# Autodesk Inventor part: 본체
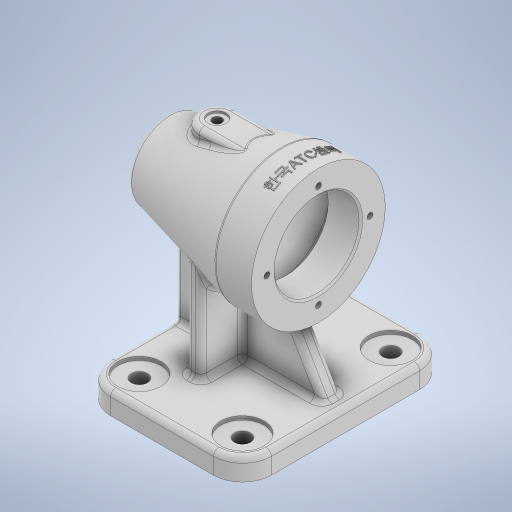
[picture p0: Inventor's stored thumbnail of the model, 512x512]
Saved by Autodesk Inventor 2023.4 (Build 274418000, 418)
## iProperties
Created: 2024-12
Part Number: 본체
Material: 일반
Document SubType Name: Modeling
Designer: EDU
Density: 1 g/cm^3
Appearance: 기본값
Author: EDU
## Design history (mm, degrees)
sketch "스케치1"
  geometry: L1 (0, 0)-(0, 21); L2 (0, 21)-(64, 37); L3 (0, 0)-(84, 0); L4 (-16.8, 0)-(100.8, 0) reference; L5 (64, 37)-(84, 37); L6 (84, 37)-(84, 0); 1 further point
  constraints: 10 end point, 2 horizontal, 1 coincident, 1 horizontal alignment, 1 perpendicular, 1 vertical
  dimensions: "d0" = 21 distance of L1.start L1.end; "d4" = 64 horizontal distance of L1.end L2.end; "d13" = 20 distance of L2.end L5.end; "d14" = 37 distance of L5.end L3.end
revolve "회전1" sketch "스케치1" stored, may be unused: angle "d6" = 90 deg
feature "쉘2" dims "d19" = 18, "d20" = 21, "d21" = 5
sketch "스케치5"
  geometry: C1 r 23.5 at (0, 0); 1 further point
  constraints: 1 centre point, 1 coincident
  dimensions: "d22" = 47 diameter of C1
extrude "돌출2" cut sketch "스케치5" distance "d23" = 18; taper "d24" = 0 deg
sketch "스케치6"
  geometry: C1 r 17.5 at (0, 0); 1 further point
  constraints: 1 centre point, 1 coincident
  dimensions: "d25" = 35 diameter of C1
extrude "돌출3" cut sketch "스케치6" distance "d26" = 10; taper "d27" = 0 deg
sketch "스케치7"
  geometry: C1 r 15.5 at (0, 0); 1 further point
  constraints: 1 centre point, 1 coincident
  dimensions: "d28" = 31 diameter of C1
extrude "돌출4" cut sketch "스케치7" distance "d29" = 3; taper "d30" = 0 deg
fillet "모깎기1" dims "d31" = 3
fillet "모깎기2" dims "d32" = 0.3
chamfer "모따기1" distance "d33" = 1; stored, may be unused: second distance "d34" = 2, angle "d35" = 45 deg
fillet "모깎기3" dims "d36" = 3
fillet "모깎기4" dims "d37" = 5
chamfer "모따기2" distance "d38" = 1; stored, may be unused: second distance "d39" = 2, angle "d40" = 45 deg
sketch "스케치8"
  geometry: C1 r 37 at (0, 0) reference; C2 r 24.5 at (0, 0) reference; A1 r 28.5 centre (0, 0) between (0, 28.5) and (0, -28.5); 3 further points
  constraints: 4 point on circle, 2 horizontal alignment, 2 vertical alignment, 1 centre point, 1 coincident
  dimensions: "d41" = 57 diameter of A1
hole "구멍1" sketch "스케치8" at (0, 28.5), (-28.5, 0), (28.5, 0), (0, -28.5) diameter "d42" = 3.242; stored, may be unused: countersink angle "d46" = 90 deg, drill point angle "d48" = 118 deg; dims "d43" = 8, "d44" = 4, "d45" = 2, "d47" = 10
node "작업 평면1"
sketch "스케치9"
  geometry: L1 (-10, 57)-(-99, 57); L2 (-99, 57)-(-99, -57); L3 (-99, -57)-(-10, -57); L4 (-10, -57)-(-10, 57); L5 (-84, 37)-(-84, -37) reference; 2 further points
  constraints: 8 end point, 2 parallel, 1 horizontal, 1 horizontal alignment, 1 midpoint, 1 perpendicular
  dimensions: "d50" = 114 distance between parallel lines of L1 L3; "d51" = 89 distance between parallel lines of L2 L4; "d52" = 15 distance between parallel lines of L2 L5
extrude "돌출5" join sketch "스케치9" distance "d53" = 12; taper "d54" = 0 deg
fillet "모깎기5" dims "d55" = 16
sketch "스케치10"
  geometry: L1 (83, 57)-(26, 57) reference; L2 (99, -41)-(99, 41) reference; L3 (26, -57)-(83, -57) reference; L4 (10, 41)-(10, -41) reference; A1 r 16 centre (26, 41) between (26, 57) and (10, 41) reference; A2 r 16 centre (83, 41) between (99, 41) and (83, 57) reference; A3 r 16 centre (83, -41) between (83, -57) and (99, -41) reference; A4 r 16 centre (26, -41) between (10, -41) and (26, -57) reference; 5 further points
  constraints: 4 coincident
hole "구멍2" sketch "스케치10" at (26, -41), (26, 41), (83, 41), (83, -41) diameter "d56" = 9; stored, may be unused: countersink angle "d60" = 90 deg, drill point angle "d62" = 118 deg; dims "d57" = 8, "d58" = 24, "d59" = 2, "d61" = 10
sketch "스케치11"
  geometry: L1 (83, 57)-(26, 57) reference; L2 (99, -41)-(99, 41) reference; L3 (26, -57)-(83, -57) reference; L4 (10, 41)-(10, -41) reference; L5 (10, 41)-(10, -41) reference; L6 (10, -5)-(39, -5); L7 (39, -5)-(39, -28); L8 (39, -28)-(47, -28); L9 (47, -28)-(47, 28); L10 (47, 28)-(39, 28); L11 (39, 28)-(39, 5); L12 (39, 5)-(10, 5); C1 r 4.5 at (83, 41) reference; C2 r 4.5 at (26, -41) reference; C3 r 4.5 at (26, 41) reference; C4 r 4.5 at (83, -41) reference; A1 r 16 centre (26, 41) between (26, 57) and (10, 41) reference; A2 r 16 centre (83, 41) between (99, 41) and (83, 57) reference; A3 r 16 centre (83, -41) between (83, -57) and (99, -41) reference; A4 r 16 centre (26, -41) between (10, -41) and (26, -57) reference; 5 further points
  constraints: 14 end point, 5 perpendicular, 4 point on line, 2 midpoint, 1 horizontal
  dimensions: "d63" = 10 distance between parallel lines of L6 L12; "d64" = 8 distance of L7.end L8.end; "d65" = 29 distance between parallel lines of L7 L4; "d66" = 56 distance between parallel lines of L10 L8; "d67" = 5 distance from line of L12 point (10, 0); "d68" = 28 distance from line of point (10, 0) L10
extrude "돌출6" join sketch "스케치11" stored distance "d69" = 12; taper "d70" = 0 deg
sketch "스케치12"
  geometry: L1 (47, -70)-(47, -16.987) reference; L2 (99, -70)-(99, -82) reference; L3 (83, -70)-(26, -70) reference; L4 (83, -70)-(99, -70) reference; L5 (99, -70)-(99, -82) reference; L6 (99, -82)-(83, -82) reference; L7 (83, -82)-(83, -70) reference; L8 (64, -37)-(84, -37) reference; L9 (0, -21)-(64, -37) reference; L10 (71, -70)-(95, -70) reference; L11 (92, -70)-(72.947, -37); 1 further point
  constraints: 2 end point, 2 point on line
  dimensions: "d71" = 7 distance of L2.start L11.start; "d72" = 60 deg angle of L4 L11
feature "리브1" sketch "스케치12" dims "d73" = 1, "d74" = 10, "d75" = 0, "d76" = 0, "d77" = 1, "d78" = 1
node "작업 평면2"
sketch "스케치13"
  geometry: L1 (-10, 37)-(-10, -37) reference; 3 further points
  constraints: 1 horizontal alignment, 1 midpoint, 1 other
  dimensions: "d79" = 9 distance from line of L1 point (-1, 0)
feature "엠보싱1" sketch "스케치13" dims "d0" = 21, "d80" = 0.5, "d81" = 0
node "작업 평면3"
sketch "스케치14"
  geometry: L1 (84, -37)-(84, 37) reference; L2 (28, 10)-(58, 10); L3 (28, -10)-(58, -10); L4 (58, 10)-(58, -10); A1 r 10 centre (28, 0) between (28, 10) and (28, -10); 2 further points
  constraints: 6 end point, 2 horizontal, 2 point on circle, 2 tangent, 1 centre point, 1 horizontal alignment, 1 midpoint, 1 vertical
  dimensions: "d83" = 20 diameter of A1; "d84" = 56 distance from line of L1 A1.centre; "d85" = 30 distance of L3.start L3.end
extrude "돌출7" join sketch "스케치14" stored distance "d86" = 10; taper "d87" = 0 deg
sketch "스케치15"
  geometry: L1 (84, -37)-(84, 37) reference; 2 further points
  constraints: 1 horizontal alignment
  dimensions: "d88" = 56 distance from line of L1 point (28, 0)
hole "구멍3" sketch "스케치15" at (28, 0) diameter "d89" = 5.1881; stored, may be unused: countersink angle "d93" = 90 deg, drill point angle "d95" = 0 deg; dims "d90" = 12, "d91" = 10, "d92" = 1, "d94" = 8
fillet "모깎기6" dims "d96" = 3
fillet "모깎기7" dims "d97" = 3
fillet "모깎기8" dims "d98" = 3
fillet "모깎기9" dims "d99" = 3
fillet "모깎기10" dims "d100" = 3
fillet "모깎기11" dims "d101" = 3
fillet "모깎기12" dims "d102" = 3
fillet "모깎기13" dims "d103" = 3
node "솔리드1"
node "투영된 루프1"
node "투영된 루프2"
node "투영된 루프3"
node "투영된 루프4"
feature "A9D066F2-1C7D-4E18-AEED-F7BC21143FA4" dims "d56" = 9, "d57" = 8, "d58" = 24, "d59" = 2, "d60" = 90 deg, "d61" = 10, "d62" = 118 deg
other parameters: "d49" = -82, "d82" = -115
